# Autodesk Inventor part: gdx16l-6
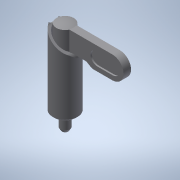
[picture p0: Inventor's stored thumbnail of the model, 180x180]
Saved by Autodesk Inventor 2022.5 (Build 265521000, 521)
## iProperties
Created: 2016-12
Part Number: gdx16l-6
Material: 一般
Document SubType Name: Modeling
Designer: imaocorp
Density: 1 g/cm^3
Appearance: 既定
Author: imaocorp
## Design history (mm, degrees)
node "gdx16l-6.x_t1"
node "gdx16l-6"
node "Base1"
